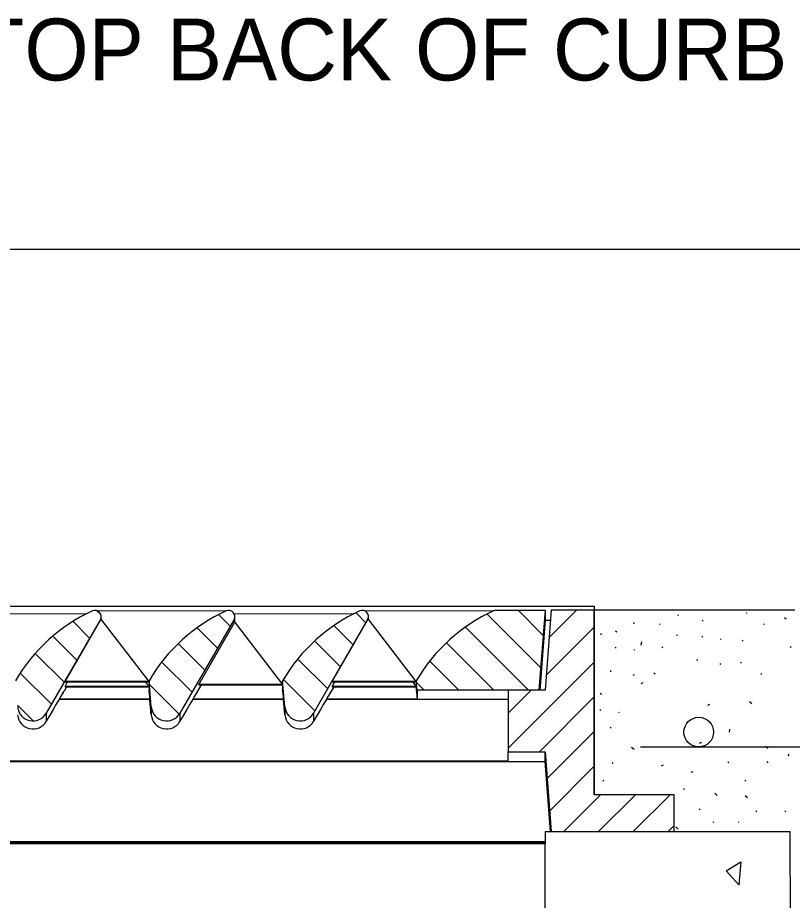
# Model space of a CAD drawing. Extents: x 49991.4 to 50029.7, y 49987.6 to 50011.4.
# Drawn here: x 50027.312 to 50028.064, y 49993.25 to 49994.106 of the extents above; entities that cross this region are included whole.
import ezdxf

# ---------------------------------------------------------------- set-up
doc = ezdxf.new("R2010")
doc.units = 0
for name, color, linetype in [('Level 1', 7, 'Continuous'), ('Level 2', 7, 'Continuous'), ('Level 4', 7, 'Continuous'), ('Level 5', 7, 'Continuous'), ('Level 7', 7, 'Continuous'), ('Level 9', 7, 'Continuous')]:
    doc.layers.add(name, color=color, linetype=linetype)

msp = doc.modelspace()

# ---------------------------------------------------------------- linework, layer by layer
at = {"layer": 'Level 1'}
for p, q in [((50026.6331, 49993.53553), (50027.87165, 49993.53553)), ((50027.77629, 49993.53141), (50027.82397, 49993.53141)), ((50027.82397, 49993.53141), (50027.81801, 49993.45391)), ((50027.82397, 49993.53141), (50027.82397, 49993.52188)), ((50027.37863, 49993.52785), (50027.26315, 49993.52795)), ((50027.51416, 49993.5307), (50027.38998, 49993.53082)), ((50027.43973, 49993.46253), (50027.39313, 49993.52331)), ((50027.39334, 49993.52486), (50027.39334, 49993.52545)), ((50027.6379, 49993.52785), (50027.52242, 49993.52795)), ((50027.52297, 49993.522), (50027.52297, 49993.52545)), ((50027.77343, 49993.5307), (50027.64925, 49993.53082)), ((50027.699, 49993.46253), (50027.65241, 49993.52331)), ((50027.65261, 49993.52486), (50027.65261, 49993.52545)), ((50027.39254, 49993.52247), (50027.34006, 49993.43156)), ((50027.35827, 49993.46241), (50027.39254, 49993.52188)), ((50027.39254, 49993.52247), (50027.39254, 49993.52188)), ((50027.52218, 49993.52247), (50027.4697, 49993.43156)), ((50027.4879, 49993.45955), (50027.52218, 49993.51902)), ((50027.52218, 49993.52247), (50027.52218, 49993.51902)), ((50027.56937, 49993.45967), (50027.52277, 49993.52045)), ((50027.65181, 49993.52247), (50027.59933, 49993.43156)), ((50027.61754, 49993.46241), (50027.65181, 49993.52188)), ((50027.65181, 49993.52247), (50027.65181, 49993.52188)), ((50027.82397, 49993.52188), (50027.81873, 49993.45391)), ((50027.82396, 49993.52176), (50027.82919, 49993.52176)), ((50027.43973, 49993.4631), (50027.43973, 49993.46253)), ((50027.44195, 49993.43771), (50027.43973, 49993.4631)), ((50027.56937, 49993.4631), (50027.56937, 49993.45967)), ((50027.57159, 49993.43771), (50027.56937, 49993.4631)), ((50027.69981, 49993.45391), (50027.699, 49993.4631)), ((50027.699, 49993.4631), (50027.699, 49993.46253)), ((50027.35972, 49993.45717), (50027.35727, 49993.45292)), ((50027.43973, 49993.46253), (50027.35827, 49993.46241)), ((50027.35827, 49993.46241), (50027.35827, 49993.46194)), ((50027.35827, 49993.46194), (50027.43973, 49993.46182)), ((50027.35827, 49993.45765), (50027.36074, 49993.46193)), ((50027.43973, 49993.45777), (50027.35827, 49993.45765)), ((50027.35827, 49993.45765), (50027.35827, 49993.45717)), ((50027.35827, 49993.45717), (50027.43973, 49993.45705)), ((50027.43973, 49993.45777), (50027.43662, 49993.46182)), ((50027.43973, 49993.46253), (50027.43973, 49993.46182)), ((50027.43973, 49993.46182), (50027.43973, 49993.45777)), ((50027.43973, 49993.45777), (50027.43973, 49993.45705)), ((50027.43973, 49993.45705), (50027.43973, 49993.45498)), ((50027.43973, 49993.45498), (50027.43973, 49993.45467)), ((50027.49046, 49993.45907), (50027.4869, 49993.45292)), ((50027.56937, 49993.45967), (50027.4879, 49993.45955)), ((50027.4879, 49993.45955), (50027.4879, 49993.45908)), ((50027.4879, 49993.45908), (50027.56937, 49993.45896)), ((50027.56937, 49993.45967), (50027.56937, 49993.45896)), ((50027.56937, 49993.45896), (50027.56937, 49993.45498)), ((50027.56937, 49993.45498), (50027.56937, 49993.45467)), ((50027.619, 49993.45717), (50027.61654, 49993.45292)), ((50027.699, 49993.46253), (50027.61754, 49993.46241)), ((50027.61754, 49993.46241), (50027.61754, 49993.46194)), ((50027.61754, 49993.46194), (50027.699, 49993.46182)), ((50027.61754, 49993.45765), (50027.62001, 49993.46193)), ((50027.699, 49993.45777), (50027.61754, 49993.45765)), ((50027.61754, 49993.45765), (50027.61754, 49993.45717)), ((50027.61754, 49993.45717), (50027.699, 49993.45705)), ((50027.699, 49993.45777), (50027.69589, 49993.46182)), ((50027.699, 49993.46253), (50027.699, 49993.46182)), ((50027.699, 49993.46182), (50027.699, 49993.45777)), ((50027.699, 49993.45777), (50027.699, 49993.45705)), ((50027.699, 49993.45705), (50027.699, 49993.45465)), ((50027.699, 49993.45465), (50027.69981, 49993.44548)), ((50027.69915, 49993.46137), (50027.70661, 49993.45391)), ((50027.69981, 49993.45391), (50027.69981, 49993.44548)), ((50027.81801, 49993.45391), (50027.69981, 49993.45391)), ((50027.35252, 49993.44513), (50027.44061, 49993.44513)), ((50027.35273, 49993.44548), (50027.44058, 49993.44548)), ((50027.44195, 49993.43771), (50027.44195, 49993.42988)), ((50027.48216, 49993.44513), (50027.57024, 49993.44513)), ((50027.48237, 49993.44548), (50027.57021, 49993.44548)), ((50027.57159, 49993.43771), (50027.57159, 49993.42988)), ((50027.6118, 49993.44513), (50027.78821, 49993.44513)), ((50027.61201, 49993.44548), (50027.69981, 49993.44548)), ((50027.34006, 49993.43156), (50027.34006, 49993.42373)), ((50027.4697, 49993.43156), (50027.4697, 49993.42373)), ((50027.59933, 49993.43156), (50027.59933, 49993.42373)), ((50027.78821, 49993.38553), (50027.78821, 49993.3943)), ((50027.78821, 49993.3943), (50027.82397, 49993.3943)), ((50026.68079, 49993.38482), (50027.82397, 49993.38482)), ((50026.71655, 49993.38553), (50027.78821, 49993.38553)), ((50028.06238, 49993.16963), (50028.06157, 49993.3168))]:
    msp.add_line(p, q, dxfattribs=at)
msp.add_circle((50027.973, 49993.41327), 0.01437, dxfattribs=at)
for centre, major_axis, ratio, start_param, end_param in [((50027.38738, 49993.52545), (0, -0.00596), 0.9998, 1.047198, 3.570389), ((50027.51701, 49993.52545), (0, -0.00596), 0.9998, 1.047198, 3.570389), ((50027.64665, 49993.52545), (0, -0.00596), 0.9998, 1.047198, 3.570389), ((50027.77629, 49993.52545), (0, -0.00596), 0.9998, 3.141593, 3.570389), ((50027.45429, 49993.37906), (0, -0.16692), 0.9998, 3.570389, 4.184803), ((50027.38738, 49993.52485), (-0.00288, -0.00523), 0.998273, 1.551926, 1.812678), ((50027.38738, 49993.52486), (0.0055, -0.0023), 0.99871, 0.133661, 0.396508), ((50027.58392, 49993.37906), (0, -0.16692), 0.9998, 3.570389, 4.184803), ((50027.71356, 49993.37906), (0, -0.16692), 0.9998, 3.570389, 4.184803), ((50027.64665, 49993.52485), (-0.00288, -0.00523), 0.998273, 1.551926, 1.812678), ((50027.64665, 49993.52486), (0.0055, -0.0023), 0.99871, 0.133661, 0.396556), ((50027.8432, 49993.37906), (0, -0.16692), 0.9998, 3.570389, 4.184803), ((50027.51701, 49993.52199), (-0.00288, -0.00523), 0.998273, 1.551926, 1.812678), ((50027.51701, 49993.522), (0.0055, -0.0023), 0.99871, 0.133661, 0.396508), ((50027.45457, 49993.45628), (0.01484, 0.00134), 0.861176, 3.138164, 3.141594), ((50027.44195, 49993.42929), (0.00261, -0.0298), 0.001736, 1.590642, 2.610005), ((50027.45349, 49993.46038), (-0.0149, 0), 0.9998, 0.393699, 0.399944), ((50027.58392, 49993.37078), (-0.16689, 0), 0.998262, 5.755558, 5.755599), ((50027.58421, 49993.45628), (0.01484, 0.00134), 0.861176, 3.138164, 3.141594), ((50027.57159, 49993.42929), (0.00261, -0.0298), 0.001736, 1.590642, 2.610005), ((50027.58313, 49993.46038), (-0.0149, 0), 0.9998, 0.393699, 0.399944), ((50027.71356, 49993.37078), (-0.16689, 0), 0.998262, 5.755558, 5.755599), ((50027.34006, 49993.42314), (0.0172, 0.0298), 0.008659, 6.268187, 7.838983), ((50027.34436, 49993.46038), (0.0149, 0), 0.9998, 5.657583, 5.759587), ((50027.4697, 49993.42314), (0.0172, 0.0298), 0.008659, 6.268187, 7.838983), ((50027.474, 49993.46038), (0.0149, 0), 0.9998, 5.645591, 5.759587), ((50027.59933, 49993.42314), (0.0172, 0.0298), 0.008659, 6.268187, 7.838983), ((50027.60364, 49993.46038), (0.0149, 0), 0.9998, 5.657583, 5.759587), ((50027.32716, 49993.43901), (0, -0.0149), 0.9998, 4.799655, 7.330383), ((50027.45679, 49993.43901), (0, -0.0149), 0.9998, 4.799655, 7.330383), ((50027.58643, 49993.43901), (0, -0.0149), 0.9998, 4.799655, 7.330383), ((50027.32716, 49993.43118), (0.01484, 0.0013), 0.01992, 3.13985, 3.141593), ((50027.32716, 49993.43118), (-0.0149, 0), 0.9998, 0.087266, 2.617994), ((50027.45679, 49993.43118), (0.01484, 0.0013), 0.01992, 3.13985, 3.141593), ((50027.45679, 49993.43118), (-0.0149, 0), 0.9998, 0.087266, 2.617994), ((50027.58643, 49993.43118), (0.01484, 0.0013), 0.01992, 3.13985, 3.141593), ((50027.58643, 49993.43118), (-0.0149, 0), 0.9998, 0.087266, 2.617994), ((50027.32716, 49993.43118), (-0.0129, 0.00745), 0.017317, 3.14159, 3.151592), ((50027.45679, 49993.43118), (-0.0129, 0.00745), 0.017317, 3.141593, 3.151592), ((50027.58643, 49993.43118), (-0.0129, 0.00745), 0.017317, 3.141593, 3.151592)]:
    msp.add_ellipse(centre, major_axis=major_axis, ratio=ratio, start_param=start_param, end_param=end_param, dxfattribs=at)
for points in [[(50027.35482, 49993.449), (50027.35528, 49993.44974), (50027.35708, 49993.45279), (50027.35655, 49993.4518), (50027.3563, 49993.45146)], [(50027.6141, 49993.449), (50027.61455, 49993.44974), (50027.61636, 49993.45279), (50027.61582, 49993.4518), (50027.61558, 49993.45146)]]:
    msp.add_open_spline(points, degree=3, dxfattribs=at)
at = {"layer": 'Level 2'}
for p, q in [((50027.7977, 49993.53141), (50027.82209, 49993.50702)), ((50027.82993, 49993.53141), (50027.82397, 49993.45391)), ((50027.8279, 49993.50496), (50027.85435, 49993.53141)), ((50027.87165, 49993.53141), (50027.82993, 49993.53141)), ((50027.87165, 49993.35257), (50027.87165, 49993.53141)), ((50027.38927, 49993.531), (50027.3927, 49993.52757)), ((50027.50751, 49993.5272), (50027.51854, 49993.51617)), ((50027.64051, 49993.52896), (50027.65005, 49993.51942)), ((50027.76771, 49993.52768), (50027.81969, 49993.47571)), ((50027.36601, 49993.52054), (50027.38212, 49993.50443)), ((50027.48655, 49993.51444), (50027.5062, 49993.49479)), ((50027.61925, 49993.5165), (50027.63771, 49993.49804)), ((50027.74666, 49993.51502), (50027.80776, 49993.45391)), ((50027.82509, 49993.46843), (50027.87165, 49993.515)), ((50027.34658, 49993.50626), (50027.36978, 49993.48305)), ((50027.46815, 49993.49913), (50027.49386, 49993.47342)), ((50027.60036, 49993.50167), (50027.62537, 49993.47667)), ((50027.72813, 49993.49983), (50027.77405, 49993.45391)), ((50027.32943, 49993.48969), (50027.35745, 49993.46168)), ((50027.45228, 49993.48128), (50027.48152, 49993.45204)), ((50027.58416, 49993.48416), (50027.61303, 49993.45529)), ((50027.71217, 49993.48207), (50027.74033, 49993.45391)), ((50027.78821, 49993.39784), (50027.87165, 49993.48128)), ((50027.31484, 49993.47056), (50027.34511, 49993.4403)), ((50027.5702, 49993.46441), (50027.60069, 49993.43391)), ((50027.44001, 49993.45983), (50027.46908, 49993.43076)), ((50027.78821, 49993.45391), (50027.78821, 49993.3943)), ((50027.82397, 49993.45391), (50027.78821, 49993.45391)), ((50027.78821, 49993.43155), (50027.81057, 49993.45391)), ((50027.81839, 49993.3943), (50027.87165, 49993.44757)), ((50027.31215, 49993.43954), (50027.32743, 49993.42426)), ((50027.82598, 49993.36818), (50027.87165, 49993.41385)), ((50027.82397, 49993.38482), (50027.82397, 49993.3943)), ((50027.82397, 49993.3943), (50027.82993, 49993.3168)), ((50027.8292, 49993.3168), (50027.82397, 49993.38482)), ((50027.82839, 49993.33687), (50027.87165, 49993.38013)), ((50027.84204, 49993.3168), (50027.87781, 49993.35257)), ((50027.94914, 49993.35257), (50027.87165, 49993.35257)), ((50027.87575, 49993.3168), (50027.91152, 49993.35257)), ((50027.90947, 49993.3168), (50027.94524, 49993.35257)), ((50027.94914, 49993.3168), (50027.94914, 49993.35257)), ((50027.94319, 49993.3168), (50027.94914, 49993.32275))]:
    msp.add_line(p, q, dxfattribs=at)
at = {"layer": 'Level 4'}
msp.add_line((50027.91647, 49993.39892), (50029.04159, 49993.39892), dxfattribs=at)
at = {"layer": 'Level 5'}
for p, q in [((50029.31478, 49993.88141), (50026.07943, 49993.88141)), ((50027.87165, 49993.53553), (50027.87165, 49993.53141)), ((50027.87165, 49993.53141), (50027.87165, 49993.35257)), ((50028.06615, 49993.53141), (50027.87165, 49993.53141))]:
    msp.add_line(p, q, dxfattribs=at)
at = {"layer": 'Level 7'}
for p, q in [((50027.82397, 49993.3168), (50027.82397, 49993.30485)), ((50027.82397, 49993.3168), (50027.82993, 49993.3168)), ((50027.82397, 49993.3168), (50028.06157, 49993.3168)), ((50027.82993, 49993.3168), (50027.94914, 49993.3168)), ((50026.68079, 49993.30723), (50027.82397, 49993.30723)), ((50026.68079, 49993.30646), (50027.82397, 49993.30646)), ((50027.82397, 49993.30485), (50026.68079, 49993.30485)), ((50027.82397, 49992.99491), (50027.82397, 49993.30485))]:
    msp.add_line(p, q, dxfattribs=at)
at = {"layer": 'Level 9'}
for p, q in [((50027.95328, 49993.52662), (50027.95246, 49993.52628)), ((50028.01967, 49993.52879), (50028.01885, 49993.52845)), ((50028.05767, 49993.52282), (50028.05616, 49993.52411)), ((50027.90988, 49993.51969), (50027.90965, 49993.51838)), ((50027.93566, 49993.51816), (50027.93485, 49993.51781)), ((50027.97739, 49993.52096), (50027.97639, 49993.52182)), ((50028.03627, 49993.51802), (50028.03545, 49993.51767)), ((50027.87808, 49993.50905), (50027.87785, 49993.50775)), ((50027.89339, 49993.51033), (50027.89238, 49993.51119)), ((50027.95226, 49993.50739), (50027.95145, 49993.50704)), ((50027.97696, 49993.50536), (50027.97595, 49993.50622)), ((50027.91742, 49993.50084), (50027.91689, 49993.49775)), ((50027.99475, 49993.5036), (50027.99393, 49993.50325)), ((50028.01609, 49993.50155), (50028.01509, 49993.50241)), ((50027.89295, 49993.49472), (50027.89195, 49993.49558)), ((50027.91075, 49993.49297), (50027.90993, 49993.49262)), ((50027.93824, 49993.49515), (50027.93724, 49993.49601)), ((50028.06258, 49993.49586), (50028.06135, 49993.49533)), ((50027.97146, 49993.48375), (50027.97124, 49993.48244)), ((50028.01455, 49993.48008), (50028.01354, 49993.48094)), ((50027.88746, 49993.47311), (50027.88723, 49993.47181)), ((50027.9945, 49993.47873), (50027.99349, 49993.47959)), ((50027.91049, 49993.46809), (50027.90949, 49993.46895)), ((50027.93054, 49993.46945), (50027.92953, 49993.47031)), ((50028.03415, 49993.46904), (50028.03314, 49993.4699)), ((50027.91878, 49993.46097), (50027.91684, 49993.46014)), ((50027.8785, 49993.44972), (50027.8775, 49993.45058)), ((50027.98348, 49993.43991), (50027.98154, 49993.43909)), ((50028.02457, 49993.44059), (50028.02221, 49993.44261)), ((50027.87806, 49993.43411), (50027.87706, 49993.43497)), ((50027.89586, 49993.43236), (50027.89504, 49993.43201)), ((50027.8879, 49993.41696), (50027.8869, 49993.41782)), ((50028.00286, 49993.41624), (50028.00233, 49993.41315)), ((50027.97363, 49993.40214), (50027.97469, 49993.40304)), ((50027.97469, 49993.40304), (50027.97554, 49993.40331)), ((50027.91029, 49993.39633), (50027.9079, 49993.39837)), ((50028.04004, 49993.39728), (50028.03768, 49993.39929)), ((50028.05994, 49993.39189), (50028.05961, 49993.38994)), ((50027.89009, 49993.38273), (50027.88908, 49993.38359)), ((50027.93847, 49993.38113), (50027.93653, 49993.38031)), ((50028.00208, 49993.38346), (50028.00108, 49993.38432)), ((50028.04039, 49993.38353), (50028.03888, 49993.38482)), ((50027.96718, 49993.37475), (50027.96525, 49993.37393)), ((50027.88092, 49993.36558), (50027.87991, 49993.36644)), ((50027.88092, 49993.36558), (50027.87991, 49993.36644)), ((50028.01862, 49993.36558), (50028.01762, 49993.36644)), ((50027.95907, 49993.35761), (50027.95807, 49993.35846)), ((50027.99088, 49993.35189), (50027.9885, 49993.35392)), ((50028.02029, 49993.34959), (50028.01793, 49993.35161)), ((50027.97449, 49993.33793), (50027.97349, 49993.33879)), ((50028.02926, 49993.33581), (50028.02825, 49993.33667)), ((50028.05744, 49993.33581), (50028.05643, 49993.33667)), ((50027.98754, 49993.32605), (50027.98672, 49993.32571)), ((50028.012, 49993.32605), (50028.01118, 49993.32571)), ((50027.95312, 49993.3192), (50027.95074, 49993.32124))]:
    msp.add_line(p, q, dxfattribs=at)
msp.add_lwpolyline([(50028.01178, 49993.26514), (50027.99941, 49993.27885), (50028.01371, 49993.28738), (50028.01178, 49993.26514)], dxfattribs=at)

# ---------------------------------------------------------------- texts
at = {"layer": 'Level 2'}
msp.add_text('TOP BACK OF CURB', height=0.06, dxfattribs=at).set_placement((50027.26981, 49994.04547))

doc.saveas('drawing.dxf')
